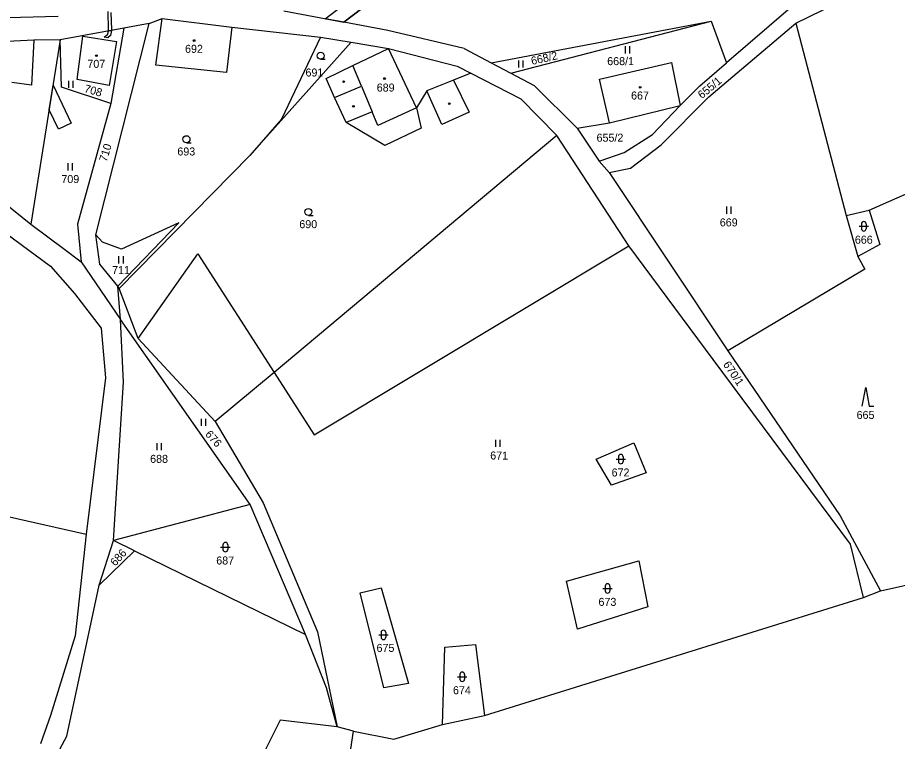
# Model space of a CAD drawing. Extents: x -670359 to -660124, y -978807 to -970072.
# Drawn here: x -668641.1 to -668454.3, y -977825.3 to -977671.6 of the extents above; entities that cross this region are included whole.
import ezdxf

# ---------------------------------------------------------------- set-up
doc = ezdxf.new("R2010")
doc.units = 0
for name, color, linetype in [('Hranice kat_území', 7, 'Continuous'), ('Hranice parcel', 7, 'Continuous'), ('Parcelní čísla', 7, 'Continuous'), ('Vnitřní kresba', 7, 'Continuous'), ('Věcná břemena k části', 7, 'Continuous'), ('Značky budov', 7, 'Continuous'), ('Značky kultur', 7, 'Continuous')]:
    doc.layers.add(name, color=color, linetype=linetype)

msp = doc.modelspace()

# ---------------------------------------------------------------- linework, layer by layer
at = {"layer": 'Hranice kat_území'}
for points in [[(-668457.87, -977793.35), (-668433.57, -977787.88)], [(-668461.52, -977794.74), (-668457.87, -977793.35)], [(-668542.02, -977819.84), (-668461.52, -977794.74)], [(-668550.89, -977821.77), (-668542.02, -977819.84)], [(-668561.25, -977824.85), (-668550.89, -977821.77)], [(-668572.57, -977841.49), (-668569.84, -977823.18)], [(-668569.84, -977823.18), (-668561.25, -977824.85)]]:
    msp.add_lwpolyline(points, dxfattribs=at)
at = {"layer": 'Hranice parcel'}
for p, q in [((-668536.38, -977683.38), (-668493.85, -977672.35)), ((-668540.55, -977681.17), (-668536.38, -977683.38)), ((-668536.38, -977683.38), (-668531.45, -977686)), ((-668506.35, -977696.41), (-668500.44, -977690.21)), ((-668512.33, -977700.2), (-668506.35, -977696.41)), ((-668517.68, -977702.09), (-668512.33, -977700.2))]:
    msp.add_line(p, q, dxfattribs=at)
for points in [[(-668571.86, -977672.56), (-668555.76, -977660.24)], [(-668475.88, -977672.75), (-668458.93, -977664.38)], [(-668584.63, -977670.12), (-668571.86, -977672.56)], [(-668477.05, -977669.51), (-668490.6, -977681.15)], [(-668632.55, -977671.35), (-668651.2, -977671.86)], [(-668613.23, -977672.8), (-668610.47, -977671.78)], [(-668611.78, -977681.65), (-668610.47, -977671.78)], [(-668610.47, -977671.78), (-668595.64, -977673.58)], [(-668562.51, -977674.34), (-668571.86, -977672.56)], [(-668540.55, -977681.17), (-668493.85, -977672.35)], [(-668494.37, -977688.42), (-668475.88, -977672.75)], [(-668493.85, -977672.35), (-668490.6, -977681.15)], [(-668475.88, -977672.75), (-668465.23, -977713.62)], [(-668618.62, -977673.79), (-668632.08, -977676.32)], [(-668624.53, -977717.7), (-668613.23, -977672.8)], [(-668618.62, -977673.79), (-668621.32, -977689.79)], [(-668613.23, -977672.8), (-668618.62, -977673.79)], [(-668595.64, -977673.58), (-668596.78, -977683.22)], [(-668595.64, -977673.58), (-668576.82, -977675.76)], [(-668546.31, -977678.11), (-668562.51, -977674.34)], [(-668637.69, -977676.34), (-668654.82, -977677.21)], [(-668632.08, -977676.32), (-668638.3, -977715.42)], [(-668637.69, -977676.34), (-668638.2, -977685.9)], [(-668632.08, -977676.32), (-668637.69, -977676.34)], [(-668631.79, -977686.32), (-668632.08, -977676.32)], [(-668628.51, -977684.73), (-668627.27, -977675.53)], [(-668627.27, -977675.53), (-668620.15, -977676.67)], [(-668576.82, -977675.76), (-668585.13, -977693.13)], [(-668576.82, -977675.76), (-668570.3, -977676.8)], [(-668620.15, -977676.67), (-668621.71, -977686.02)], [(-668570.3, -977676.8), (-668591.8, -977700.84)], [(-668570.3, -977676.8), (-668562.4, -977678.11)], [(-668569.98, -977681.76), (-668562.4, -977678.11)], [(-668562.4, -977678.11), (-668547.8, -977681.9)], [(-668546.31, -977678.11), (-668540.55, -977681.17)], [(-668596.78, -977683.22), (-668611.78, -977681.65)], [(-668575.65, -977684.5), (-668569.98, -977681.76)], [(-668547.8, -977681.9), (-668544.92, -977683.38)], [(-668517.55, -977684.65), (-668502.28, -977681.1)], [(-668502.28, -977681.1), (-668500.44, -977690.21)], [(-668496.29, -977686.04), (-668490.6, -977681.15)], [(-668544.92, -977683.38), (-668548.55, -977684.84)], [(-668544.92, -977683.38), (-668534.27, -977688.86)], [(-668638.2, -977685.9), (-668642.36, -977685.33)], [(-668621.71, -977686.02), (-668628.51, -977684.73)], [(-668573.82, -977688.51), (-668575.65, -977684.5)], [(-668548.55, -977684.84), (-668545.26, -977691.68)], [(-668515.47, -977693.92), (-668517.55, -977684.65)], [(-668621.32, -977689.79), (-668631.79, -977686.32)], [(-668554.23, -977687.12), (-668556.44, -977690.72)], [(-668551.04, -977694.27), (-668554.23, -977687.12)], [(-668531.45, -977686), (-668522.32, -977695.04)], [(-668500.44, -977690.21), (-668496.29, -977686.04)], [(-668571.37, -977693.88), (-668573.82, -977688.51)], [(-668534.27, -977688.86), (-668526.62, -977696.65)], [(-668504.5, -977698.63), (-668494.37, -977688.42)], [(-668621.32, -977689.79), (-668628.41, -977715.46)], [(-668556.44, -977690.72), (-668555.47, -977695.08)], [(-668515.47, -977693.92), (-668500.44, -977690.21)], [(-668585.13, -977693.13), (-668591.8, -977700.84)], [(-668545.26, -977691.68), (-668551.04, -977694.27)], [(-668563.13, -977698.73), (-668571.37, -977693.88)], [(-668555.47, -977695.08), (-668563.13, -977698.73)], [(-668522.32, -977695.04), (-668515.47, -977693.92)], [(-668522.32, -977695.04), (-668517.68, -977702.09)], [(-668526.62, -977696.65), (-668586.69, -977746.97)], [(-668511.35, -977720.08), (-668526.62, -977696.65)], [(-668659.7, -977698.24), (-668638.3, -977715.42)], [(-668511, -977703.53), (-668504.5, -977698.63)], [(-668591.8, -977700.84), (-668619.55, -977729.15)], [(-668517.68, -977702.09), (-668515.52, -977704.49)], [(-668515.52, -977704.49), (-668511, -977703.53)], [(-668515.52, -977704.49), (-668490.35, -977742.35)], [(-668460.3, -977712.51), (-668440.7, -977703.84)], [(-668654.53, -977709.38), (-668634.16, -977724.39)], [(-668465.23, -977713.62), (-668460.3, -977712.51)], [(-668465.23, -977713.62), (-668462.73, -977722.35)], [(-668460.3, -977712.51), (-668458.08, -977719.79)], [(-668638.3, -977715.42), (-668631.43, -977720.64)], [(-668628.41, -977715.46), (-668627.68, -977723.45)], [(-668619.85, -977728.6), (-668606.9, -977715.15)], [(-668606.9, -977715.15), (-668619.09, -977720.77)], [(-668623.67, -977723.94), (-668624.53, -977717.7)], [(-668624.53, -977717.7), (-668623.1, -977719.25)], [(-668619.09, -977720.77), (-668623.1, -977719.25)], [(-668631.43, -977720.64), (-668627.68, -977723.45)], [(-668493.46, -977744.24), (-668511.35, -977720.08)], [(-668458.08, -977719.79), (-668462.73, -977722.35)], [(-668462.73, -977722.35), (-668461.23, -977725.04)], [(-668634.16, -977724.39), (-668629.06, -977730.17)], [(-668627.68, -977723.45), (-668619.3, -977735.7)], [(-668619.85, -977728.6), (-668623.67, -977723.94)], [(-668461.23, -977725.04), (-668490.35, -977742.35)], [(-668619.55, -977729.15), (-668619.85, -977728.6)], [(-668619.3, -977735.7), (-668619.85, -977728.6)], [(-668629.06, -977730.17), (-668623.4, -977737.55)], [(-668615.55, -977739.75), (-668619.55, -977729.15)], [(-668591.77, -977775.03), (-668619.3, -977735.7)], [(-668618.64, -977749.04), (-668619.3, -977735.7)], [(-668623.4, -977737.55), (-668622.47, -977748.11)], [(-668599.16, -977757.41), (-668615.55, -977739.75)], [(-668490.35, -977742.35), (-668466.44, -977777.44)], [(-668464.25, -977783.44), (-668493.46, -977744.24)], [(-668586.69, -977746.97), (-668599.16, -977757.41)], [(-668622.47, -977748.11), (-668626.59, -977781.3)], [(-668620.79, -977782.66), (-668618.64, -977749.04)], [(-668599.16, -977757.41), (-668589.03, -977774.65)], [(-668518.31, -977765.37), (-668510.26, -977761.89)], [(-668510.26, -977761.89), (-668507.68, -977768.31)], [(-668515.06, -977770.93), (-668518.31, -977765.37)], [(-668692.75, -977766.4), (-668626.59, -977781.3)], [(-668507.68, -977768.31), (-668515.06, -977770.93)], [(-668591.77, -977775.03), (-668620.79, -977782.66)], [(-668580.01, -977802.66), (-668591.77, -977775.03)], [(-668589.03, -977774.65), (-668577.43, -977802.03)], [(-668466.44, -977777.44), (-668457.87, -977793.35)], [(-668626.59, -977781.3), (-668628.9, -977802.9)], [(-668623.82, -977792.18), (-668620.79, -977782.66)], [(-668616.3, -977784.86), (-668620.79, -977782.66)], [(-668623.82, -977792.18), (-668616.3, -977784.86)], [(-668616.3, -977784.86), (-668580.01, -977802.66)], [(-668461.52, -977794.74), (-668464.25, -977783.44)], [(-668524.59, -977791.32), (-668509.22, -977786.98)], [(-668509.22, -977786.98), (-668507.32, -977796.73)], [(-668630.67, -977824.25), (-668623.82, -977792.18)], [(-668522.23, -977801.49), (-668524.59, -977791.32)], [(-668568.41, -977793.78), (-668563.97, -977792.74)], [(-668563.35, -977813.97), (-668568.41, -977793.78)], [(-668563.97, -977792.74), (-668558.11, -977813.03)], [(-668507.32, -977796.73), (-668522.23, -977801.49)], [(-668628.9, -977802.9), (-668634.16, -977819.84)], [(-668575.52, -977813.94), (-668580.01, -977802.66)], [(-668577.43, -977802.03), (-668573.26, -977822.26)], [(-668550.89, -977821.77), (-668550.39, -977805.3)], [(-668550.39, -977805.3), (-668543.89, -977804.73)], [(-668543.89, -977804.73), (-668542.02, -977819.84)], [(-668573.26, -977822.26), (-668575.52, -977813.94)], [(-668558.11, -977813.03), (-668563.35, -977813.97)], [(-668634.16, -977819.84), (-668636.27, -977825.84)], [(-668585.38, -977820.8), (-668597.1, -977844.23)], [(-668573.26, -977822.26), (-668585.38, -977820.8)], [(-668569.84, -977823.18), (-668573.26, -977822.26)], [(-668638.79, -977839.27), (-668630.67, -977824.25)]]:
    msp.add_lwpolyline(points, dxfattribs=at)
at = {"layer": 'Vnitřní kresba'}
for points in [[(-668556.44, -977690.72), (-668562.4, -977678.11)], [(-668568.15, -977686.15), (-668569.98, -977681.76)], [(-668548.55, -977684.84), (-668554.23, -977687.12)], [(-668573.82, -977688.51), (-668568.15, -977686.15)], [(-668568.15, -977686.15), (-668565.88, -977691.59)], [(-668556.44, -977690.72), (-668564.66, -977694.52)], [(-668565.88, -977691.59), (-668571.37, -977693.88)], [(-668564.66, -977694.52), (-668565.88, -977691.59)], [(-668578.19, -977760.23), (-668511.35, -977720.08)], [(-668615.55, -977739.75), (-668602.87, -977721.74)], [(-668602.87, -977721.74), (-668586.69, -977746.97)], [(-668586.69, -977746.97), (-668578.19, -977760.23)]]:
    msp.add_lwpolyline(points, dxfattribs=at)
at = {"layer": 'Věcná břemena k části'}
for p, q in [((-668621.82, -977674.09), (-668621.94, -977670.27)), ((-668621.32, -977670.51), (-668621.2, -977674.13)), ((-668621.98, -977675.08), (-668621.87, -977674.4)), ((-668621.87, -977674.4), (-668621.82, -977674.09)), ((-668621.23, -977674.28), (-668621.42, -977675.4)), ((-668621.2, -977674.13), (-668621.23, -977674.28)), ((-668622.74, -977675.74), (-668621.98, -977675.08)), ((-668621.98, -977675.89), (-668622.74, -977675.74)), ((-668621.42, -977675.4), (-668621.98, -977675.89)), ((-668633.61, -977685.91), (-668629.77, -977694)), ((-668632.48, -977695.29), (-668634.44, -977691.16)), ((-668629.77, -977694), (-668632.48, -977695.29))]:
    msp.add_line(p, q, dxfattribs=at)
for points in [[(-668575.83, -977671.8), (-668557.84, -977658.04)], [(-668555.76, -977660.24), (-668571.86, -977672.56)], [(-668571.86, -977672.56), (-668575.83, -977671.8)], [(-668621.87, -977674.4), (-668621.23, -977674.28)], [(-668621.23, -977674.28), (-668621.87, -977674.4)], [(-668634.44, -977691.16), (-668633.61, -977685.91)]]:
    msp.add_lwpolyline(points, dxfattribs=at)
at = {"layer": 'Značky budov'}
for centre in [(-668603.66, -977676.45), (-668624.4, -977679.64), (-668563.23, -977684.51), (-668508.94, -977686.37)]:
    msp.add_circle(centre, 0.175, dxfattribs=at)
at = {"layer": 'Značky kultur'}
for p, q in [((-668512.15, -977677.66), (-668512.15, -977679.16)), ((-668511.15, -977679.16), (-668511.15, -977677.66)), ((-668576.8, -977680.42), (-668575.8, -977680.42)), ((-668534.8, -977680.66), (-668534.8, -977682.16)), ((-668533.8, -977682.16), (-668533.8, -977680.66)), ((-668630.33, -977685.02), (-668630.33, -977686.52)), ((-668629.33, -977686.52), (-668629.33, -977685.02)), ((-668605.29, -977698.16), (-668604.29, -977698.16)), ((-668630.46, -977702.52), (-668630.46, -977704.02)), ((-668629.46, -977704.02), (-668629.46, -977702.52)), ((-668490.64, -977711.73), (-668490.64, -977713.23)), ((-668489.64, -977713.23), (-668489.64, -977711.73)), ((-668579.39, -977713.61), (-668578.39, -977713.61)), ((-668461.96, -977715.41), (-668461.96, -977716.41)), ((-668460.96, -977715.41), (-668460.96, -977716.41)), ((-668462.46, -977715.91), (-668460.46, -977715.91)), ((-668619.69, -977722.28), (-668619.69, -977723.78)), ((-668618.69, -977723.78), (-668618.69, -977722.28)), ((-668602.14, -977756.79), (-668602.14, -977758.29)), ((-668601.14, -977758.29), (-668601.14, -977756.79)), ((-668611.57, -977761.97), (-668611.57, -977763.47)), ((-668610.57, -977763.47), (-668610.57, -977761.97)), ((-668539.67, -977761.26), (-668539.67, -977762.76)), ((-668538.67, -977762.76), (-668538.67, -977761.26)), ((-668514.07, -977765.36), (-668512.07, -977765.36)), ((-668513.57, -977764.86), (-668513.57, -977765.86)), ((-668512.57, -977764.86), (-668512.57, -977765.86)), ((-668598.03, -977784.06), (-668596.03, -977784.06)), ((-668597.53, -977783.56), (-668597.53, -977784.56)), ((-668596.53, -977783.56), (-668596.53, -977784.56)), ((-668516.36, -977792.35), (-668516.36, -977793.35)), ((-668515.36, -977792.35), (-668515.36, -977793.35)), ((-668516.86, -977792.85), (-668514.86, -977792.85)), ((-668564.45, -977802.72), (-668562.45, -977802.72)), ((-668563.95, -977802.22), (-668563.95, -977803.22)), ((-668562.95, -977802.22), (-668562.95, -977803.22)), ((-668547.73, -977811.62), (-668545.73, -977811.62)), ((-668547.23, -977811.12), (-668547.23, -977812.12)), ((-668546.23, -977811.12), (-668546.23, -977812.12))]:
    msp.add_line(p, q, dxfattribs=at)
msp.add_lwpolyline([(-668461.8, -977754.13), (-668461.05, -977750.13), (-668460.3, -977754.13), (-668459.3, -977754.13)], dxfattribs=at)
for centre, radius in [((-668603.66, -977676.45), 0.175), ((-668624.4, -977679.64), 0.175), ((-668576.8, -977679.67), 0.75), ((-668571.92, -977685.18), 0.175), ((-668563.23, -977684.51), 0.175), ((-668508.94, -977686.37), 0.175), ((-668569.82, -977690.43), 0.175), ((-668549.48, -977689.86), 0.175), ((-668605.29, -977697.41), 0.75), ((-668579.39, -977712.86), 0.75)]:
    msp.add_circle(centre, radius, dxfattribs=at)
for centre, start, end in [((-668461.46, -977715.41), 0, 180), ((-668461.46, -977716.41), 180, 0), ((-668513.07, -977764.86), 0, 180), ((-668513.07, -977765.86), 180, 0), ((-668597.03, -977783.56), 0, 180), ((-668597.03, -977784.56), 180, 0), ((-668515.86, -977792.35), 0, 180), ((-668515.86, -977793.35), 180, 0), ((-668563.45, -977802.22), 0, 180), ((-668563.45, -977803.22), 180, 0), ((-668546.73, -977811.12), 0, 180), ((-668546.73, -977812.12), 180, 0)]:
    msp.add_arc(centre, 0.5, start, end, dxfattribs=at)

# ---------------------------------------------------------------- texts
at = {"layer": 'Parcelní čísla'}
for s, p in [('692', (-668605.59, -977679.05)), ('668/1', (-668515.94, -977681.67)), ('707', (-668626.33, -977682.24)), ('691', (-668580.01, -977684.08)), ('689', (-668564.88, -977687.28)), ('667', (-668510.87, -977688.97)), ('655/2', (-668518.2, -977697.93)), ('693', (-668607.22, -977700.86)), ('709', (-668631.85, -977706.72)), ('690', (-668581.32, -977716.31)), ('669', (-668492.03, -977715.93)), ('666', (-668463.35, -977719.61)), ('711', (-668621.08, -977726.05)), ('665', (-668462.98, -977756.83)), ('671', (-668540.78, -977765.46)), ('688', (-668613, -977766.17)), ('672', (-668515, -977769.06)), ('687', (-668598.96, -977787.76)), ('673', (-668517.79, -977796.55)), ('675', (-668564.92, -977806.33)), ('674', (-668548.69, -977815.32))]:
    msp.add_text(s, height=1.7, dxfattribs=at).set_placement(p)
for s, rotation, p in [('668/2', 12.6, (-668531.91, -977681.63)), ('708', 344.6591, (-668627.12, -977687.39)), ('655/1', 39.6, (-668495.84, -977688.91)), ('710', 72.6844, (-668622.26, -977702.31)), ('670/1', 304.1653, (-668491.4, -977745.27)), ('676', 311.6661, (-668601.42, -977760.17)), ('686', 47.6507, (-668620.41, -977788.23))]:
    msp.add_text(s, height=1.7, rotation=rotation, dxfattribs=at).set_placement(p)

doc.saveas('drawing.dxf')
